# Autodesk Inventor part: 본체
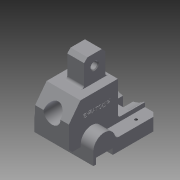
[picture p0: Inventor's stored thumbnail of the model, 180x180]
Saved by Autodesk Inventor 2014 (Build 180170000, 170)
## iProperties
Created: 2016-11
Part Number: 본체
Material: Generic
Document SubType Name: Modeling
Designer: user
Density: 1 g/cm^3
Appearance: Default
Author: user
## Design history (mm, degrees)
sketch "Sketch1"
  geometry: L1 (0, 0)-(0, 48); L2 (0, 48)-(-44.373, 48); L3 (-44.373, 48)-(-58, 30); L4 (-58, 30)-(-58, 0); L5 (-58, 0)-(0, 0)
  constraints: 10 end point, 2 parallel, 1 perpendicular, 1 vertical
  dimensions: "d8" = 58 distance between parallel lines of L4 L1; "d9" = 48 distance between parallel lines of L5 L2; "d10" = 30 distance of L3.end L4.end; "d11" = 142.872 deg angle of L4 L3
extrude "Extrusion1" new body sketch "Sketch1" stored distance "d12" = 40; taper "d13" = 0 deg
sketch "Sketch6"
  geometry: L1 (-44, 8)-(32, 8); L2 (32, 8)-(32, -12); L3 (32, -12)-(-44, -12); L4 (-44, -12)-(-44, 8); L5 (-58, 0)-(-58, 30) reference; L6 (-44.373, 48)-(0, 48) reference; 1 further point
  constraints: 8 end point, 2 parallel, 1 horizontal, 1 perpendicular
  dimensions: "d19" = 20 distance of L1.end L2.end; "d20" = 76 distance of L2.end L3.end; "d21" = 90 distance between parallel lines of L2 L5; "d22" = 60 distance between parallel lines of L3 L6
extrude "Extrusion3" join sketch "Sketch6" stored distance "d23" = 70; taper "d24" = 0 deg
sketch "Sketch9"
  geometry: L1 (0, 0)-(15, 0); L2 (15, 0)-(15, 5); L3 (15, 5)-(0, 5); L4 (0, 5)-(0, 0); 1 further point
  constraints: 8 end point, 2 parallel, 1 horizontal, 1 perpendicular
  dimensions: "d29" = 5 distance of L3.end L1.start; "d30" = 15 distance of L2.end L3.end
extrude "Extrusion4" cut sketch "Sketch9" stored distance "d31" = 70; taper "d32" = 0 deg
mirror "Mirror1"
sketch "Sketch10"
  geometry: L1 (0, 8)-(32, 8) reference; L2 (32, 8)-(32, -12) reference; L3 (32, -12)-(-44, -12) reference; L4 (-44, -12)-(-44, 0) reference; L5 (-44, 0)-(-58, 0) reference; L6 (-58, 0)-(-58, 30) reference; L7 (-58, 30)-(-44.373, 48) reference; L8 (-44.373, 48)-(0, 48) reference; L9 (0, 48)-(0, 8) reference; L10 (32, 3)-(-44, 3) reference; L11 (-44, -12)-(-44, 3) reference; L12 (-44, 3)-(-18, 3); A1 r 13 centre (-31, 3) between (-18, 3) and (-44, 3); 1 further point
  constraints: 3 end point, 2 point on circle, 2 point on line, 1 centre point, 1 perpendicular, 1 tangent
  dimensions: "d33" = 26 diameter of A1
extrude "Extrusion5" join sketch "Sketch10" stored distance "d34" = 70; taper "d35" = 0 deg
sketch "Sketch11"
  geometry: L1 (-3, -44)-(12, -44) reference; L2 (12, -44)-(12, 32) reference; L3 (12, -41)-(5, -41); L4 (5, -41)-(5, -21); L5 (5, -21)-(12, -21); L6 (12, -21)-(12, -41); 1 further point
  constraints: 8 end point, 2 parallel, 1 horizontal, 1 perpendicular, 1 point on line
  dimensions: "d36" = 3 distance between parallel lines of L3 L1; "d37" = 20 distance between parallel lines of L5 L3; "d38" = 7 distance between parallel lines of L2 L4
extrude "Extrusion6" cut sketch "Sketch11" stored distance "d39" = 70; taper "d40" = 0 deg
chamfer "Chamfer1" distance "d41" = 4; stored, may be unused: second distance "d42" = 2, angle "d43" = 45 deg
sketch "Sketch12"
  geometry: L1 (0, 8)-(32, 8) reference; L2 (32, 8)-(32, -12) reference; L3 (32, -12)-(-21, -12) reference; L4 (-21, -12)-(-21, -5) reference; L5 (-21, -5)-(-41, -5) reference; L6 (-41, -5)-(-41, -12) reference; L7 (-41, -12)-(-44, -12) reference; L8 (-44, -12)-(-44, 0) reference; L9 (-44, 0)-(-54, 0) reference; L10 (-54, 0)-(-58, 4) reference; L11 (-58, 4)-(-58, 30) reference; L12 (-58, 30)-(-44.373, 48) reference; L13 (-44.373, 48)-(0, 48) reference; L14 (0, 48)-(0, 8) reference; L15 (0, 8)-(32, 8) reference; L16 (32, 8)-(32, -12) reference; L17 (32, -12)-(-21, -12) reference; L18 (-21, -12)-(-21, -5) reference; L19 (-21, -5)-(-41, -5) reference; L20 (-41, -5)-(-41, -12) reference; L21 (-41, -12)-(-44, -12) reference; L22 (-44, -12)-(-44, 0) reference; L23 (-44, 0)-(-54, 0) reference; L24 (-54, 0)-(-58, 4) reference; L25 (-58, 4)-(-58, 30) reference; L26 (-58, 30)-(-44.373, 48) reference; L27 (-44.373, 48)-(0, 48) reference; L28 (0, 48)-(0, 8) reference; L29 (0, 48)-(-44.373, 48) reference; L30 (-5, 48)-(-30, 48); L31 (-30, 48)-(-30, 78); L32 (-30, 78)-(-5, 78); L33 (-5, 78)-(-5, 48); 1 further point
  constraints: 8 end point, 2 parallel, 1 horizontal, 1 perpendicular, 1 point on line
  dimensions: "d44" = 25 distance of L31.end L32.end; "d45" = 90 distance between parallel lines of L3 L32; "d46" = 30 distance of L30.end L31.end (derived); "d102" = 5 distance between parallel lines of L14 L33
extrude "Extrusion7" join sketch "Sketch12" stored distance "d48" = 20; taper "d49" = 0 deg
chamfer "Chamfer2" distance "d50" = 4; stored, may be unused: second distance "d51" = 2, angle "d52" = 45 deg
sketch "Sketch13"
  geometry: L1 (55, 60)-(-15, 60) reference; L2 (55, 60)-(55, 45) reference; L3 (0, 48)-(40, 48) reference; C1 r 14.5 at (20, 18); 1 further point
  constraints: 1 centre point
  dimensions: "d53" = 29 diameter of C1; "d55" = 35 distance from line of C1.centre L2; "d56" = 30 distance from line of C1.centre L3
extrude "Extrusion8" cut sketch "Sketch13" distance "d57" = 7; taper "d58" = 0 deg
sketch "Sketch14"
  geometry: C1 r 14.5 at (0, 0) reference; C2 r 10 at (0, 0); 1 further point
  constraints: 1 centre point, 1 coincident
  dimensions: "d59" = 20 diameter of C2
extrude "Extrusion9" cut sketch "Sketch14" stored distance "d60" = 7; taper "d61" = 0 deg
chamfer "Chamfer3" distance "d62" = 1; stored, may be unused: second distance "d63" = 2, angle "d64" = 45 deg
sketch "Sketch15"
  geometry: L1 (-74, -30)-(-48, -30) reference; L2 (12, 32)-(12, -21) reference; C1 r 4 at (-65, -17.5); 1 further point
  constraints: 1 centre point
  dimensions: "d65" = 8 diameter of C1; "d66" = 12.5 distance from line of C1.centre L1; "d67" = 77 distance from line of C1.centre L2
extrude "Extrusion10" cut sketch "Sketch15" stored distance "d68" = 7; taper "d69" = 0 deg
chamfer "Chamfer4" distance "d70" = 1; stored, may be unused: second distance "d71" = 2, angle "d72" = 45 deg
fillet "Fillet1" dims "d73" = 5
fillet "Fillet2" dims "d74" = 3
sketch "Sketch16"
  geometry: C1 r 29 at (35, -42); C2 r 11 at (35, -42) reference; 1 further point
  constraints: 1 centre point, 1 concentric
  dimensions: "d75" = 58 diameter of C1
extrude "Extrusion11" cut sketch "Sketch16" distance "d76" = 18; taper "d77" = 0 deg
sketch "Sketch17"
  geometry: L1 (70, 0)-(0, 0) reference; L2 (29, 0)-(41, 0); L3 (41, 0)-(41, -17.5); L4 (41, -17.5)-(29, -17.5); L5 (29, -17.5)-(29, 0); 2 further points
  constraints: 8 end point, 2 parallel, 1 horizontal, 1 midpoint, 1 perpendicular, 1 point on line, 1 vertical alignment
  dimensions: "d78" = 12 distance of L3.end L4.end; "d79" = 17.5 distance of L4.end L2.start
extrude "Extrusion12" cut sketch "Sketch17" distance "d80" = 18; taper "d81" = 0 deg
fillet "Fillet3" dims "d82" = 3
chamfer "Chamfer5" distance "d83" = 5; stored, may be unused: second distance "d84" = 2, angle "d85" = 45 deg
sketch "Sketch18"
  geometry: L1 (0, 45.708)-(10, 45.708) reference; L2 (-50, 45.708)-(-40, 45.708) reference; L3 (-20, 13.708)-(-20, 49.368); 2 further points
  constraints: 2 end point, 1 perpendicular
  dimensions: "d86" = 18 distance from line of point (7.5, 27.708) L1; "d87" = 18 distance from line of point (-47.5, 27.708) L2; "d88" = 55 distance of point (7.5, 27.708) point (-47.5, 27.708); "d89" = 27.5 distance from line of point (-47.5, 27.708) L3; "d90" = 27.5 distance from line of point (7.5, 27.708) L3 (derived)
hole "Hole1" sketch "Sketch18" at (7.5, 27.708), (-47.5, 27.708) diameter "d91" = 3.242; stored, may be unused: countersink angle "d95" = 90 deg, drill point angle "d97" = 118 deg; dims "d92" = 20, "d93" = 4, "d94" = 2, "d96" = 8
sketch "Sketch19"
  geometry: L1 (-11, 0)-(-48, 0) reference; L2 (-48, 0)-(-48, -44.373) reference; 2 further points
  constraints: 1 other
  dimensions: "d98" = 25 distance from line of point (-30, -25) L1; "d99" = 18 distance from line of point (-30, -25) L2
emboss "Emboss1" sketch "Sketch19" dims "d100" = 0.5, "d101" = 0
body "Solid1"
node "Project Cut Edges3"
node "Project Cut Edges4"
node "Project Cut Edges5"
